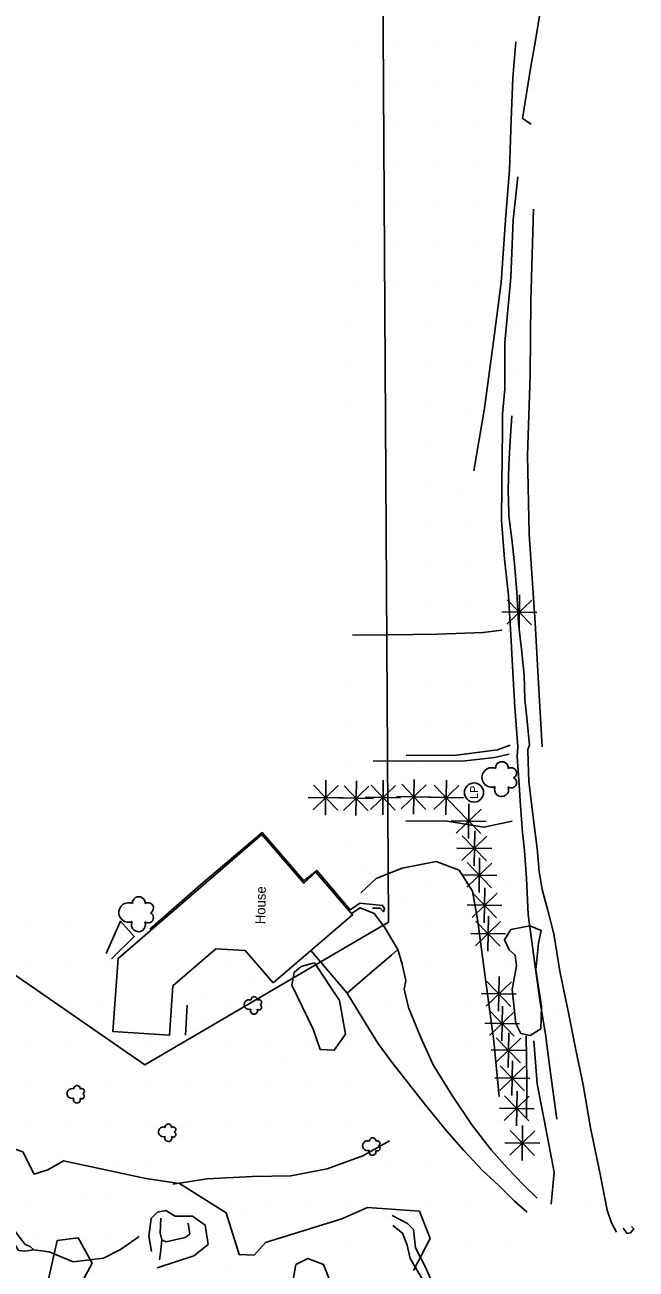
# Model space of a CAD drawing. Extents: x 19528164 to 19545171, y 7585743 to 7602745.
# Drawn here: x 19532104 to 19532410, y 7590372 to 7590997 of the extents above; entities that cross this region are included whole.
import ezdxf

# ---------------------------------------------------------------- set-up
doc = ezdxf.new("R2010")
doc.units = 0
for name, color, linetype in [('PhoBreakLine', 7, 'Continuous'), ('PhoBuilding', 7, 'Continuous'), ('PhoConcreteSlab', 7, 'Continuous'), ('PhoEdgeEntrancePaved', 7, 'Continuous'), ('PhoISAEPoints', 7, 'Continuous'), ('PhoNotesDesign', 7, 'Continuous'), ('PhoSurveyLimits', 7, 'Continuous'), ('PhoVegetation', 7, 'Continuous'), ('SurEdgeEntranceUnpaved', 7, 'Continuous'), ('SurNaturalCells', 7, 'Continuous'), ('SurROWRail', 7, 'Continuous')]:
    doc.layers.add(name, color=color, linetype=linetype)

# ---------------------------------------------------------------- blocks, each defined once
blk = doc.blocks.new('TRDC')
at = {"layer": 'PhoVegetation'}
for centre, radius, start, end in [((-6, -1.1), 3.52, 65.4824, 294.5175), ((0.1, 4), 4.92, 338.2051, 201.7949), ((4.9, -1.1), 3.21, 265.9982, 94.0018), ((-2.4, -5.9), 2.68, 142.7501, 335.3223), ((2.5, -5.8), 2.67, 206.5242, 35.4033)]:
    blk.add_arc(centre, radius, start, end, dxfattribs=at)

msp = doc.modelspace()

# ---------------------------------------------------------------- linework, layer by layer
at = {"layer": 'PhoBreakLine'}
msp.add_line((19532185.1, 7590504.37), (19532184.19, 7590489.31), dxfattribs=at)
for points in [[(19532317.34, 7591063.46), (19532335.15, 7591065.25), (19532360.71, 7591063.83), (19532366.68, 7591060.96), (19532369.67, 7591054.9), (19532369.96, 7591045.05), (19532366.25, 7591027.71), (19532364.14, 7591014.4), (19532359.67, 7590987.73), (19532357.59, 7590975.61), (19532353.29, 7590949.6), (19532357.68, 7590946.7)], [(19532350, 7590988.08), (19532348.6, 7590969.99), (19532347.68, 7590948.91), (19532346.89, 7590923.8), (19532344.77, 7590898.59), (19532342.59, 7590867.21), (19532338.87, 7590837.57), (19532334.23, 7590804.07), (19532328.9, 7590772.67)], [(19532351, 7590920.16), (19532348.73, 7590898.71), (19532347.44, 7590869.65), (19532344.57, 7590837.13), (19532344.46, 7590813.7), (19532343.4, 7590801.29)], [(19532363.18, 7590634.03), (19532361.39, 7590665.85), (19532359.78, 7590696.48), (19532356.75, 7590740.79), (19532355.87, 7590780.24), (19532357.29, 7590820.64), (19532357.47, 7590858.05), (19532358.93, 7590904.07)], [(19532343.4, 7590801.29), (19532343.37, 7590792.53), (19532343.11, 7590780.09), (19532342.99, 7590765.19), (19532342.84, 7590747.83), (19532344.29, 7590728.22), (19532346.27, 7590709.97), (19532347.7, 7590687.18), (19532348.67, 7590668.37), (19532349.47, 7590653.76), (19532351.06, 7590634.2), (19532350.73, 7590629.21), (19532351.69, 7590614.98), (19532352.3, 7590604.42), (19532353.44, 7590590.97), (19532354.34, 7590581.82), (19532355.32, 7590568), (19532356.23, 7590549.78), (19532359.66, 7590523.74), (19532362.24, 7590505.58), (19532364.99, 7590489.73), (19532366.95, 7590473.93), (19532370.65, 7590447.02)], [(19532400.56, 7590390.34), (19532397.95, 7590394.96), (19532395.91, 7590401.41), (19532392.41, 7590419.5), (19532387.57, 7590442.64), (19532383.76, 7590464.28), (19532380.08, 7590481.87), (19532376.4, 7590500.39), (19532372.09, 7590521.38), (19532369.13, 7590540.08), (19532365.95, 7590552.57), (19532363.31, 7590562.3), (19532361.66, 7590571.43), (19532360.69, 7590583.02), (19532358.94, 7590597.28), (19532356.59, 7590616.63), (19532356.16, 7590626.55), (19532356.08, 7590632.75), (19532356.92, 7590634.89), (19532355.66, 7590646.93), (19532354.59, 7590658.02), (19532354.23, 7590670.03), (19532352.8, 7590683.11), (19532351.41, 7590695.97), (19532350.57, 7590711.7), (19532349.29, 7590726.12), (19532347.96, 7590738.29), (19532346.47, 7590749.98), (19532346.52, 7590751.32), (19532346.52, 7590751.32), (19532346.22, 7590762.86), (19532346.43, 7590775.39), (19532347.19, 7590787.7), (19532347.98, 7590800.17)], [(19532268.06, 7590690.14), (19532286, 7590690.28), (19532310.66, 7590690.64), (19532333.6, 7590691.43), (19532342.99, 7590692.61)], [(19532278.41, 7590626.98), (19532302.08, 7590626.85), (19532324.59, 7590626.91), (19532339.39, 7590628.66), (19532346.61, 7590630.38)], [(19532295.01, 7590629.75), (19532318.93, 7590629.67), (19532340.82, 7590632.54), (19532347.25, 7590634.78)], [(19532348.2, 7590596.74), (19532333.97, 7590593.72), (19532315.56, 7590596.72), (19532294.87, 7590596.86)], [(19532166.36, 7590542.54), (19532191.76, 7590564.7), (19532222.79, 7590590.93), (19532232.26, 7590579.89), (19532243.57, 7590566.73), (19532250.15, 7590571.98), (19532266.95, 7590552.13)], [(19532272.17, 7590560.75), (19532280, 7590567.88), (19532292.92, 7590573.16), (19532309.99, 7590576.52), (19532321.53, 7590572.16), (19532328.21, 7590561.46), (19532330.91, 7590546.25), (19532333.63, 7590526.06), (19532338.96, 7590486.19), (19532341.6, 7590458.46)], [(19532266.95, 7590552.13), (19532271.78, 7590555.57), (19532283.13, 7590554.35), (19532284.05, 7590552.92), (19532283.62, 7590551.17), (19532281.92, 7590552.97), (19532278.11, 7590553.03)], [(19532144.38, 7590530.24), (19532151.69, 7590546.46), (19532158.52, 7590538.78), (19532147.08, 7590527.54)], [(19532355.37, 7590447.42), (19532355.62, 7590466.22), (19532355.14, 7590488.97)], [(19532367.73, 7590404.4), (19532369.24, 7590420.41), (19532364.89, 7590443.23), (19532360.69, 7590464.77), (19532359.1, 7590486.34)], [(19532177.83, 7590414.47), (19532195.15, 7590417.17), (19532217.85, 7590418.34), (19532237.08, 7590418.64), (19532255.36, 7590422.04), (19532273.2, 7590428.64), (19532286.65, 7590436.1)], [(19532073.24, 7590377.95), (19532084.01, 7590380.5), (19532089.98, 7590385.67), (19532096.4, 7590387.86), (19532100.48, 7590381.03), (19532103.68, 7590380.73), (19532108.2, 7590381.47), (19532106.39, 7590383.1), (19532103.89, 7590384.14), (19532100.95, 7590387.81), (19532098.38, 7590391.08), (19532094.91, 7590393.39), (19532092.96, 7590396.58), (19532089.53, 7590396.5), (19532085.81, 7590395.6), (19532084.05, 7590395.55), (19532080.66, 7590396.48), (19532077.97, 7590398.32), (19532075.71, 7590402.42)], [(19532170.02, 7590372.34), (19532188.46, 7590378.47), (19532195.72, 7590384.13), (19532194.19, 7590393.83), (19532187.7, 7590398.39), (19532179.04, 7590398.36), (19532174.35, 7590401.18), (19532170.2, 7590400.4), (19532167.07, 7590397.25), (19532165.88, 7590388.23), (19532167.22, 7590380.67)], [(19532310.39, 7590329.98), (19532309.35, 7590344.06), (19532310.11, 7590360.5), (19532304.61, 7590373.08), (19532299.72, 7590382.39), (19532298.65, 7590391.57), (19532295.72, 7590394.62), (19532287.91, 7590398.6)], [(19532171.94, 7590397.41), (19532171.5, 7590389.8), (19532172.44, 7590386.48), (19532174.48, 7590385.44), (19532178.83, 7590386.46), (19532184.13, 7590387.64), (19532186.47, 7590389.38), (19532185.54, 7590394.91)], [(19532288.27, 7590393.6), (19532293.08, 7590389.87), (19532295.51, 7590383.77), (19532297.08, 7590377.09), (19532302.98, 7590366.85), (19532305.87, 7590359.01), (19532306.27, 7590344.88), (19532305.94, 7590330.27), (19532304.87, 7590329.92), (19532303.89, 7590330.48)], [(19532407.99, 7590393.09), (19532409.16, 7590391.93), (19532407.64, 7590390), (19532405.83, 7590389.62), (19532403.81, 7590392.4)], [(19532108.2, 7590381.47), (19532115.82, 7590380.48), (19532127.88, 7590375.48), (19532143.1, 7590377.33), (19532151.7, 7590381.59), (19532161, 7590388.18)], [(19532172.44, 7590386.48), (19532171.96, 7590381.28), (19532171.2, 7590376.41)]]:
    msp.add_lwpolyline(points, dxfattribs=at)
at = {"layer": 'PhoBuilding'}
msp.add_lwpolyline([(19532228.18, 7590515.59), (19532268.08, 7590549.62), (19532249.69, 7590571.12), (19532243.69, 7590565.48), (19532222.65, 7590589.97), (19532150.42, 7590527.73), (19532147.88, 7590491.06), (19532176.28, 7590489.17), (19532177.98, 7590514), (19532199.48, 7590532.54), (19532214.22, 7590531.68)], close=True, dxfattribs=at)
at = {"layer": 'PhoConcreteSlab'}
msp.add_lwpolyline([(19532239.7, 7590374), (19532245.71, 7590377.02), (19532253.56, 7590374), (19532260.84, 7590355.52), (19532243.84, 7590349.74), (19532236.01, 7590353.17)], close=True, dxfattribs=at)
at = {"layer": 'PhoEdgeEntrancePaved'}
for points in [[(19532290.77, 7590532.24), (19532284.07, 7590543.47), (19532279.02, 7590550.38), (19532271.92, 7590553.24), (19532267.54, 7590550.31)], [(19532247.09, 7590531.67), (19532265.4, 7590510.36), (19532276.84, 7590520.26), (19532287.68, 7590529.36), (19532290.77, 7590532.24)]]:
    msp.add_lwpolyline(points, dxfattribs=at)
at = {"layer": 'PhoISAEPoints'}
for p, q in [((19532310, 7590985), (19532310, 7590985)), ((19532330, 7590985), (19532330, 7590985)), ((19532310, 7590965), (19532310, 7590965)), ((19532330, 7590965), (19532330, 7590965)), ((19532310, 7590945), (19532310, 7590945)), ((19532330, 7590945), (19532330, 7590945)), ((19532310, 7590925), (19532310, 7590925)), ((19532330, 7590925), (19532330, 7590925)), ((19532310, 7590905), (19532310, 7590905)), ((19532330, 7590905), (19532330, 7590905)), ((19532310, 7590885), (19532310, 7590885)), ((19532330, 7590885), (19532330, 7590885)), ((19532310, 7590865), (19532310, 7590865)), ((19532330, 7590865), (19532330, 7590865)), ((19532305, 7590845), (19532305, 7590845)), ((19532325, 7590845), (19532325, 7590845)), ((19532351.13, 7590844.83), (19532351.13, 7590844.83)), ((19532305, 7590825), (19532305, 7590825)), ((19532325, 7590825), (19532325, 7590825)), ((19532350.38, 7590823.02), (19532350.38, 7590823.02)), ((19532307.14, 7590804.45), (19532307.14, 7590804.45)), ((19532324.5, 7590802.26), (19532324.5, 7590802.26)), ((19532285, 7590785), (19532285, 7590785)), ((19532306.99, 7590784.5), (19532306.99, 7590784.5)), ((19532352.09, 7590777.91), (19532352.09, 7590777.91)), ((19532285, 7590765), (19532285, 7590765)), ((19532306.14, 7590765.27), (19532306.14, 7590765.27)), ((19532322.93, 7590761.76), (19532322.93, 7590761.76)), ((19532285, 7590745), (19532285, 7590745)), ((19532306.01, 7590744.81), (19532306.01, 7590744.81)), ((19532325, 7590745), (19532325, 7590745)), ((19532285, 7590725), (19532285, 7590725)), ((19532306.82, 7590724.07), (19532306.82, 7590724.07)), ((19532325, 7590725), (19532325, 7590725)), ((19532285, 7590705), (19532285, 7590705)), ((19532306.07, 7590704.65), (19532306.07, 7590704.65)), ((19532325, 7590705), (19532325, 7590705)), ((19532265, 7590665), (19532265, 7590665)), ((19532285, 7590665), (19532285, 7590665)), ((19532305, 7590665), (19532305, 7590665)), ((19532325, 7590665), (19532325, 7590665)), ((19532265, 7590645), (19532265, 7590645)), ((19532285, 7590645), (19532285, 7590645)), ((19532305, 7590645), (19532305, 7590645)), ((19532325, 7590645), (19532325, 7590645)), ((19532265, 7590625), (19532265, 7590625)), ((19532265, 7590605), (19532265, 7590605)), ((19532285, 7590605), (19532285, 7590605)), ((19532305, 7590605), (19532305, 7590605)), ((19532325, 7590605), (19532325, 7590605)), ((19532265, 7590585), (19532265, 7590585)), ((19532285, 7590585), (19532285, 7590585)), ((19532325, 7590585), (19532325, 7590585)), ((19532272.5, 7590573.95), (19532272.5, 7590573.95)), ((19532305, 7590565), (19532305, 7590565)), ((19532345, 7590565), (19532345, 7590565)), ((19532293.03, 7590558.85), (19532293.03, 7590558.85)), ((19532105, 7590545), (19532105, 7590545)), ((19532125, 7590545), (19532125, 7590545)), ((19532305, 7590545), (19532305, 7590545)), ((19532345, 7590545), (19532345, 7590545)), ((19532105, 7590525), (19532105, 7590525)), ((19532125, 7590525), (19532125, 7590525)), ((19532145, 7590525), (19532145, 7590525)), ((19532205, 7590525), (19532205, 7590525)), ((19532305, 7590525), (19532305, 7590525)), ((19532345, 7590525), (19532345, 7590525)), ((19532218.9, 7590516.89), (19532218.9, 7590516.89)), ((19532105, 7590505), (19532105, 7590505)), ((19532125, 7590505), (19532125, 7590505)), ((19532141.14, 7590506.48), (19532141.14, 7590506.48)), ((19532192.53, 7590508.61), (19532192.53, 7590508.61)), ((19532205, 7590505), (19532205, 7590505)), ((19532225, 7590505), (19532225, 7590505)), ((19532245, 7590505), (19532245, 7590505)), ((19532285, 7590505), (19532285, 7590505)), ((19532325, 7590505), (19532325, 7590505)), ((19532344.17, 7590505.28), (19532344.17, 7590505.28)), ((19532369.7, 7590501.51), (19532369.7, 7590501.51)), ((19532192.05, 7590497.76), (19532192.05, 7590497.76)), ((19532349.33, 7590497.23), (19532349.33, 7590497.23)), ((19532190.02, 7590488.38), (19532190.02, 7590488.38)), ((19532346.47, 7590489.45), (19532346.47, 7590489.45)), ((19532105, 7590485), (19532105, 7590485)), ((19532125, 7590485), (19532125, 7590485)), ((19532145, 7590485), (19532145, 7590485)), ((19532165, 7590485), (19532165, 7590485)), ((19532185, 7590485), (19532185, 7590485)), ((19532205, 7590485), (19532205, 7590485)), ((19532225, 7590485), (19532225, 7590485)), ((19532245, 7590485), (19532245, 7590485)), ((19532265, 7590485), (19532265, 7590485)), ((19532325, 7590485), (19532325, 7590485)), ((19532234.92, 7590474.88), (19532234.92, 7590474.88)), ((19532346.64, 7590474.38), (19532346.64, 7590474.38)), ((19532370.44, 7590476.58), (19532370.44, 7590476.58)), ((19532105, 7590465), (19532105, 7590465)), ((19532125, 7590465), (19532125, 7590465)), ((19532145, 7590465), (19532145, 7590465)), ((19532165, 7590465), (19532165, 7590465)), ((19532185, 7590465), (19532185, 7590465)), ((19532205, 7590465), (19532205, 7590465)), ((19532225, 7590465), (19532225, 7590465)), ((19532245, 7590465), (19532245, 7590465)), ((19532265, 7590465), (19532265, 7590465)), ((19532105, 7590445), (19532105, 7590445)), ((19532125, 7590445), (19532125, 7590445)), ((19532145, 7590445), (19532145, 7590445)), ((19532165, 7590445), (19532165, 7590445)), ((19532185, 7590445), (19532185, 7590445)), ((19532205, 7590445), (19532205, 7590445)), ((19532225, 7590445), (19532225, 7590445)), ((19532245, 7590445), (19532245, 7590445)), ((19532265, 7590445), (19532265, 7590445)), ((19532345, 7590445), (19532345, 7590445)), ((19532105, 7590425), (19532105, 7590425)), ((19532122.33, 7590429.03), (19532122.33, 7590429.03)), ((19532149.43, 7590425.05), (19532149.43, 7590425.05)), ((19532165, 7590425), (19532165, 7590425)), ((19532285, 7590425), (19532285, 7590425)), ((19532305, 7590425), (19532305, 7590425)), ((19532105, 7590405), (19532105, 7590405)), ((19532131.94, 7590406.96), (19532131.94, 7590406.96)), ((19532146.94, 7590407.57), (19532146.94, 7590407.57)), ((19532205, 7590405), (19532205, 7590405)), ((19532225, 7590405), (19532225, 7590405)), ((19532245, 7590405), (19532245, 7590405)), ((19532265, 7590405), (19532265, 7590405)), ((19532305, 7590405), (19532305, 7590405)), ((19532325, 7590405), (19532325, 7590405)), ((19532385, 7590405), (19532385, 7590405)), ((19532213.72, 7590400.25), (19532213.72, 7590400.25)), ((19532110.88, 7590388.96), (19532110.88, 7590388.96)), ((19532144.68, 7590387.5), (19532144.68, 7590387.5)), ((19532210.28, 7590386.48), (19532210.28, 7590386.48)), ((19532228.73, 7590386.29), (19532228.73, 7590386.29)), ((19532125, 7590385), (19532125, 7590385)), ((19532265, 7590385), (19532265, 7590385)), ((19532325, 7590385), (19532325, 7590385)), ((19532345, 7590385), (19532345, 7590385)), ((19532203.88, 7590372.84), (19532203.88, 7590372.84))]:
    msp.add_line(p, q, dxfattribs=at)
at = {"layer": 'PhoSurveyLimits'}
msp.add_lwpolyline([(19531492.52, 7590939.32), (19532163.83, 7590474.32), (19532286.15, 7590546.02), (19532286.15, 7590546.02), (19532279.02, 7591748.83), (19532392.75, 7591747.67), (19532933.44, 7591193.6), (19533437.31, 7591046.07), (19533734.35, 7591292.49), (19534091.1, 7591487.7), (19534567.67, 7591635.69)], dxfattribs=at)
at = {"layer": 'PhoVegetation'}
for p, q in [((19532358.04, 7590707.7), (19532345.48, 7590695.53)), ((19532357.85, 7590695.33), (19532345.68, 7590707.9)), ((19532351.63, 7590692.87), (19532351.9, 7590710.36)), ((19532360.51, 7590701.47), (19532343.02, 7590701.75)), ((19532351.76, 7590701.61), (19532351.76, 7590701.61)), ((19532254.45, 7590599.76), (19532254.72, 7590617.25)), ((19532269.76, 7590599.46), (19532270.04, 7590616.96)), ((19532283.23, 7590599.83), (19532283.5, 7590617.32)), ((19532298.69, 7590600.16), (19532298.97, 7590617.65)), ((19532314.94, 7590599.82), (19532315.21, 7590617.31)), ((19532260.87, 7590614.59), (19532248.3, 7590602.42)), ((19532260.67, 7590602.22), (19532248.5, 7590614.79)), ((19532276.18, 7590614.3), (19532263.62, 7590602.12)), ((19532275.99, 7590601.93), (19532263.82, 7590614.49)), ((19532289.65, 7590614.66), (19532277.08, 7590602.49)), ((19532289.45, 7590602.29), (19532277.28, 7590614.86)), ((19532305.11, 7590614.99), (19532292.55, 7590602.82)), ((19532304.92, 7590602.62), (19532292.74, 7590615.19)), ((19532321.36, 7590614.65), (19532308.8, 7590602.48)), ((19532321.16, 7590602.28), (19532308.99, 7590614.85)), ((19532263.33, 7590608.37), (19532245.84, 7590608.64)), ((19532254.59, 7590608.51), (19532254.59, 7590608.51)), ((19532278.65, 7590608.07), (19532261.16, 7590608.35)), ((19532269.9, 7590608.21), (19532269.9, 7590608.21)), ((19532292.11, 7590608.43), (19532274.62, 7590608.71)), ((19532283.37, 7590608.57), (19532283.37, 7590608.57)), ((19532307.57, 7590608.77), (19532290.08, 7590609.04)), ((19532298.83, 7590608.9), (19532298.83, 7590608.9)), ((19532323.82, 7590608.43), (19532306.33, 7590608.7)), ((19532315.08, 7590608.57), (19532315.08, 7590608.57)), ((19532326.21, 7590587.97), (19532326.48, 7590605.46)), ((19532332.63, 7590602.8), (19532320.07, 7590590.63)), ((19532332.43, 7590590.43), (19532320.26, 7590602.99)), ((19532335.09, 7590596.57), (19532317.6, 7590596.85)), ((19532326.35, 7590596.71), (19532326.35, 7590596.71)), ((19532335.51, 7590589.13), (19532322.95, 7590576.96)), ((19532335.32, 7590576.76), (19532323.14, 7590589.33)), ((19532329.09, 7590574.3), (19532329.37, 7590591.79)), ((19532337.97, 7590582.91), (19532320.48, 7590583.18)), ((19532329.23, 7590583.04), (19532329.23, 7590583.04)), ((19532338.01, 7590575.66), (19532325.45, 7590563.49)), ((19532337.82, 7590563.29), (19532325.64, 7590575.86)), ((19532331.59, 7590560.83), (19532331.87, 7590578.32)), ((19532340.47, 7590569.44), (19532322.98, 7590569.71)), ((19532331.73, 7590569.58), (19532331.73, 7590569.58)), ((19532340.4, 7590548.18), (19532328.23, 7590560.74)), ((19532334.18, 7590545.71), (19532334.45, 7590563.21)), ((19532343.06, 7590554.32), (19532325.57, 7590554.6)), ((19532340.59, 7590560.55), (19532328.03, 7590548.37)), ((19532334.31, 7590554.46), (19532334.31, 7590554.46)), ((19532335.98, 7590531.43), (19532336.25, 7590548.93)), ((19532342.4, 7590546.27), (19532329.83, 7590534.09)), ((19532342.2, 7590533.9), (19532330.03, 7590546.46)), ((19532344.86, 7590540.04), (19532327.37, 7590540.32)), ((19532336.12, 7590540.18), (19532336.12, 7590540.18)), ((19532341.37, 7590501.2), (19532341.64, 7590518.69)), ((19532347.78, 7590516.03), (19532335.22, 7590503.86)), ((19532347.59, 7590503.66), (19532335.42, 7590516.23)), ((19532350.25, 7590509.81), (19532332.76, 7590510.08)), ((19532341.5, 7590509.95), (19532341.5, 7590509.95)), ((19532349.41, 7590501.18), (19532336.85, 7590489.01)), ((19532349.22, 7590488.81), (19532337.05, 7590501.37)), ((19532343, 7590486.35), (19532343.27, 7590503.84)), ((19532351.88, 7590494.95), (19532334.39, 7590495.23)), ((19532343.13, 7590495.09), (19532343.13, 7590495.09)), ((19532352.6, 7590487.75), (19532340.04, 7590475.58)), ((19532352.41, 7590475.38), (19532340.23, 7590487.95)), ((19532346.18, 7590472.92), (19532346.46, 7590490.41)), ((19532355.07, 7590481.53), (19532337.57, 7590481.8)), ((19532346.32, 7590481.67), (19532346.32, 7590481.67)), ((19532354.52, 7590473.69), (19532341.96, 7590461.52)), ((19532354.32, 7590461.32), (19532342.15, 7590473.89)), ((19532348.1, 7590458.86), (19532348.37, 7590476.35)), ((19532356.98, 7590467.47), (19532339.49, 7590467.74)), ((19532348.24, 7590467.6), (19532348.24, 7590467.6)), ((19532350.35, 7590443.69), (19532350.63, 7590461.19)), ((19532356.77, 7590458.52), (19532344.21, 7590446.35)), ((19532356.58, 7590446.16), (19532344.41, 7590458.72)), ((19532359.24, 7590452.3), (19532341.75, 7590452.58)), ((19532350.49, 7590452.44), (19532350.49, 7590452.44)), ((19532353.18, 7590426.35), (19532353.45, 7590443.85)), ((19532359.6, 7590441.19), (19532347.03, 7590429.01)), ((19532359.4, 7590428.82), (19532347.23, 7590441.38)), ((19532362.06, 7590434.96), (19532344.57, 7590435.24)), ((19532353.32, 7590435.1), (19532353.32, 7590435.1))]:
    msp.add_line(p, q, dxfattribs=at)
for points in [[(19532350.01, 7590495.07), (19532348.14, 7590512.09), (19532350.28, 7590524), (19532349.73, 7590529.36), (19532346.71, 7590532.15), (19532344.29, 7590537.06), (19532347.58, 7590542.27), (19532357.01, 7590544.21), (19532362.81, 7590541.87), (19532361.45, 7590535.42), (19532359.98, 7590521.96), (19532362.87, 7590503.83), (19532362.58, 7590492.43), (19532357.24, 7590489.14), (19532352.46, 7590490.12)], [(19532249.03, 7590525.49), (19532261.56, 7590506.62), (19532264.52, 7590489.74), (19532258.93, 7590481.74), (19532251.86, 7590482.02), (19532248.34, 7590492.17), (19532237.6, 7590514.3), (19532238.76, 7590520.75), (19532242.37, 7590523.75)]]:
    msp.add_lwpolyline(points, close=True, dxfattribs=at)
for points in [[(19532059.83, 7590424.68), (19532017.79, 7590457.01), (19531976.2, 7590493.01), (19531975.56, 7590501.24), (19531979.17, 7590506.77), (19531998.73, 7590508.56), (19532016.83, 7590481.37), (19532048.7, 7590458.79), (19532085.63, 7590436.48), (19532102.58, 7590430.61), (19532108.27, 7590419.45), (19532115.24, 7590421.69), (19532123.08, 7590426.21), (19532164.41, 7590417.19), (19532181.23, 7590414.7)], [(19532181.23, 7590414.7), (19532204.7, 7590400.1), (19532211.14, 7590379.14), (19532218.67, 7590378.75), (19532224.37, 7590385.13), (19532262.68, 7590397.08), (19532275.6, 7590402.74), (19532301.63, 7590400.85), (19532307.09, 7590387.11), (19532298.72, 7590371.13)], [(19532131.5, 7590363.87), (19532137.46, 7590374.77), (19532130.34, 7590387.41), (19532119.82, 7590386.12), (19532115.24, 7590365.12)]]:
    msp.add_lwpolyline(points, dxfattribs=at)
for centre, radius, start, end in [((19532337.95, 7590618.63), 4.92, 67.30121, 290.89106), ((19532343.05, 7590623.35), 3.21, 355.09433, 183.09795), ((19532347.76, 7590620.87), 2.67, 295.6203, 124.49948), ((19532347.75, 7590616.04), 2.68, 231.84628, 64.41848), ((19532342.88, 7590612.52), 3.52, 154.57854, 23.61368), ((19532155.73, 7590550.83), 4.92, 67.30121, 290.89106), ((19532160.83, 7590555.55), 3.21, 355.09433, 183.09795), ((19532165.54, 7590553.07), 2.67, 295.6203, 124.49948), ((19532165.54, 7590548.24), 2.68, 231.84628, 64.41848), ((19532160.66, 7590544.72), 3.52, 154.57854, 23.61368), ((19532275.62, 7590433.72), 2.46, 67.30121, 290.89106), ((19532278.18, 7590436.07), 1.6, 355.09433, 183.09795), ((19532280.53, 7590434.84), 1.34, 295.6203, 124.49948), ((19532278.09, 7590430.66), 1.76, 154.57854, 23.61368), ((19532280.53, 7590432.42), 1.34, 231.84628, 64.41848)]:
    msp.add_arc(centre, radius, start, end, dxfattribs=at)
at = {"layer": 'SurEdgeEntranceUnpaved'}
for p, q in [((19532270, 7590985), (19532270, 7590985)), ((19532290, 7590985), (19532290, 7590985)), ((19532270, 7590965), (19532270, 7590965)), ((19532290, 7590965), (19532290, 7590965)), ((19532270, 7590945), (19532270, 7590945)), ((19532290, 7590945), (19532290, 7590945)), ((19532270, 7590925), (19532270, 7590925)), ((19532290, 7590925), (19532290, 7590925)), ((19532270, 7590905), (19532270, 7590905)), ((19532290, 7590905), (19532290, 7590905)), ((19532270, 7590885), (19532270, 7590885)), ((19532290, 7590885), (19532290, 7590885)), ((19532270, 7590865), (19532270, 7590865)), ((19532290, 7590865), (19532290, 7590865)), ((19532265, 7590845), (19532265, 7590845)), ((19532285, 7590845), (19532285, 7590845)), ((19532265, 7590825), (19532265, 7590825)), ((19532285, 7590825), (19532285, 7590825)), ((19532265, 7590805), (19532265, 7590805))]:
    msp.add_line(p, q, dxfattribs=at)
at = {"layer": 'SurNaturalCells'}
msp.add_circle((19532329.02, 7590611.07), 4.8, dxfattribs=at)
at = {"layer": 'SurROWRail'}
for points in [[(19532360.72, 7590407.31), (19532353.97, 7590413.85), (19532345.61, 7590422.65), (19532337.59, 7590431.71), (19532327.88, 7590444.18), (19532318, 7590458.91), (19532308.62, 7590474.36), (19532302.14, 7590488.37), (19532296.13, 7590503.07), (19532294.07, 7590512.39), (19532294.83, 7590516.66), (19532293.04, 7590524.92), (19532290.77, 7590532.24)], [(19532355.71, 7590400.32), (19532349.38, 7590405.81), (19532341.32, 7590413.87), (19532333.27, 7590421.35), (19532323.93, 7590431.35), (19532315.25, 7590441.19), (19532304.91, 7590453.89), (19532287.81, 7590475.74), (19532280.82, 7590485.27), (19532273.18, 7590497.48), (19532265.4, 7590510.36)]]:
    msp.add_lwpolyline(points, dxfattribs=at)

# ---------------------------------------------------------------- block references
at = {"layer": 'PhoVegetation', "xscale": 0.499999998, "yscale": 0.499999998, "rotation": 89.09614373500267}
for p in [(19532218.16, 7590504.52), (19532129.27, 7590459.88), (19532175.12, 7590440.59)]:
    msp.add_blockref('TRDC', p, dxfattribs=at)

# ---------------------------------------------------------------- texts
at = {"layer": 'PhoNotesDesign'}
msp.add_text('House', height=4.92, rotation=89.09614, dxfattribs=at).set_placement((19532224.26, 7590544.92))
at = {"layer": 'SurNaturalCells'}
msp.add_text('LP', height=3.999, rotation=89.09614, dxfattribs=at).set_placement((19532330.97, 7590607.86))

doc.saveas('drawing.dxf')
